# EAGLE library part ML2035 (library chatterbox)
Serial Input Programmable Sine Wave Generator
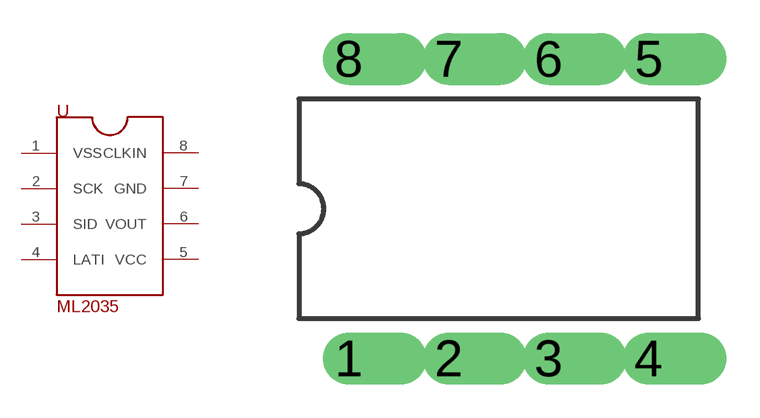
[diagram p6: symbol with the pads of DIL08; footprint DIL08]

Designator prefix -

## ML2035P08  [DIL08]
1  VSS  pwr
2  SCK  pas
3  SID  pas
4  LATI  pas
5  VCC  pwr
6  VOUT  pas
7  GND  pwr
8  CLKIN  pas

## Footprint DIL08 (pad centres in mm)
Dual In Line 8
drill 0.813 offset: 1 -3.81,-3.81; 2 -1.27,-3.81; 3 1.27,-3.81; 4 3.81,-3.81; 5 3.81,3.81; 6 1.27,3.81; 7 -1.27,3.81; 8 -3.81,3.81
